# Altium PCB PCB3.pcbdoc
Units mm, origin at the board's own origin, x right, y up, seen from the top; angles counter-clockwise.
Board outline 92.7 x 92.7 mm, 2 copper layers (Top Layer, Bottom Layer); 80 components, 48 nets, 283 pads, 345 vias.
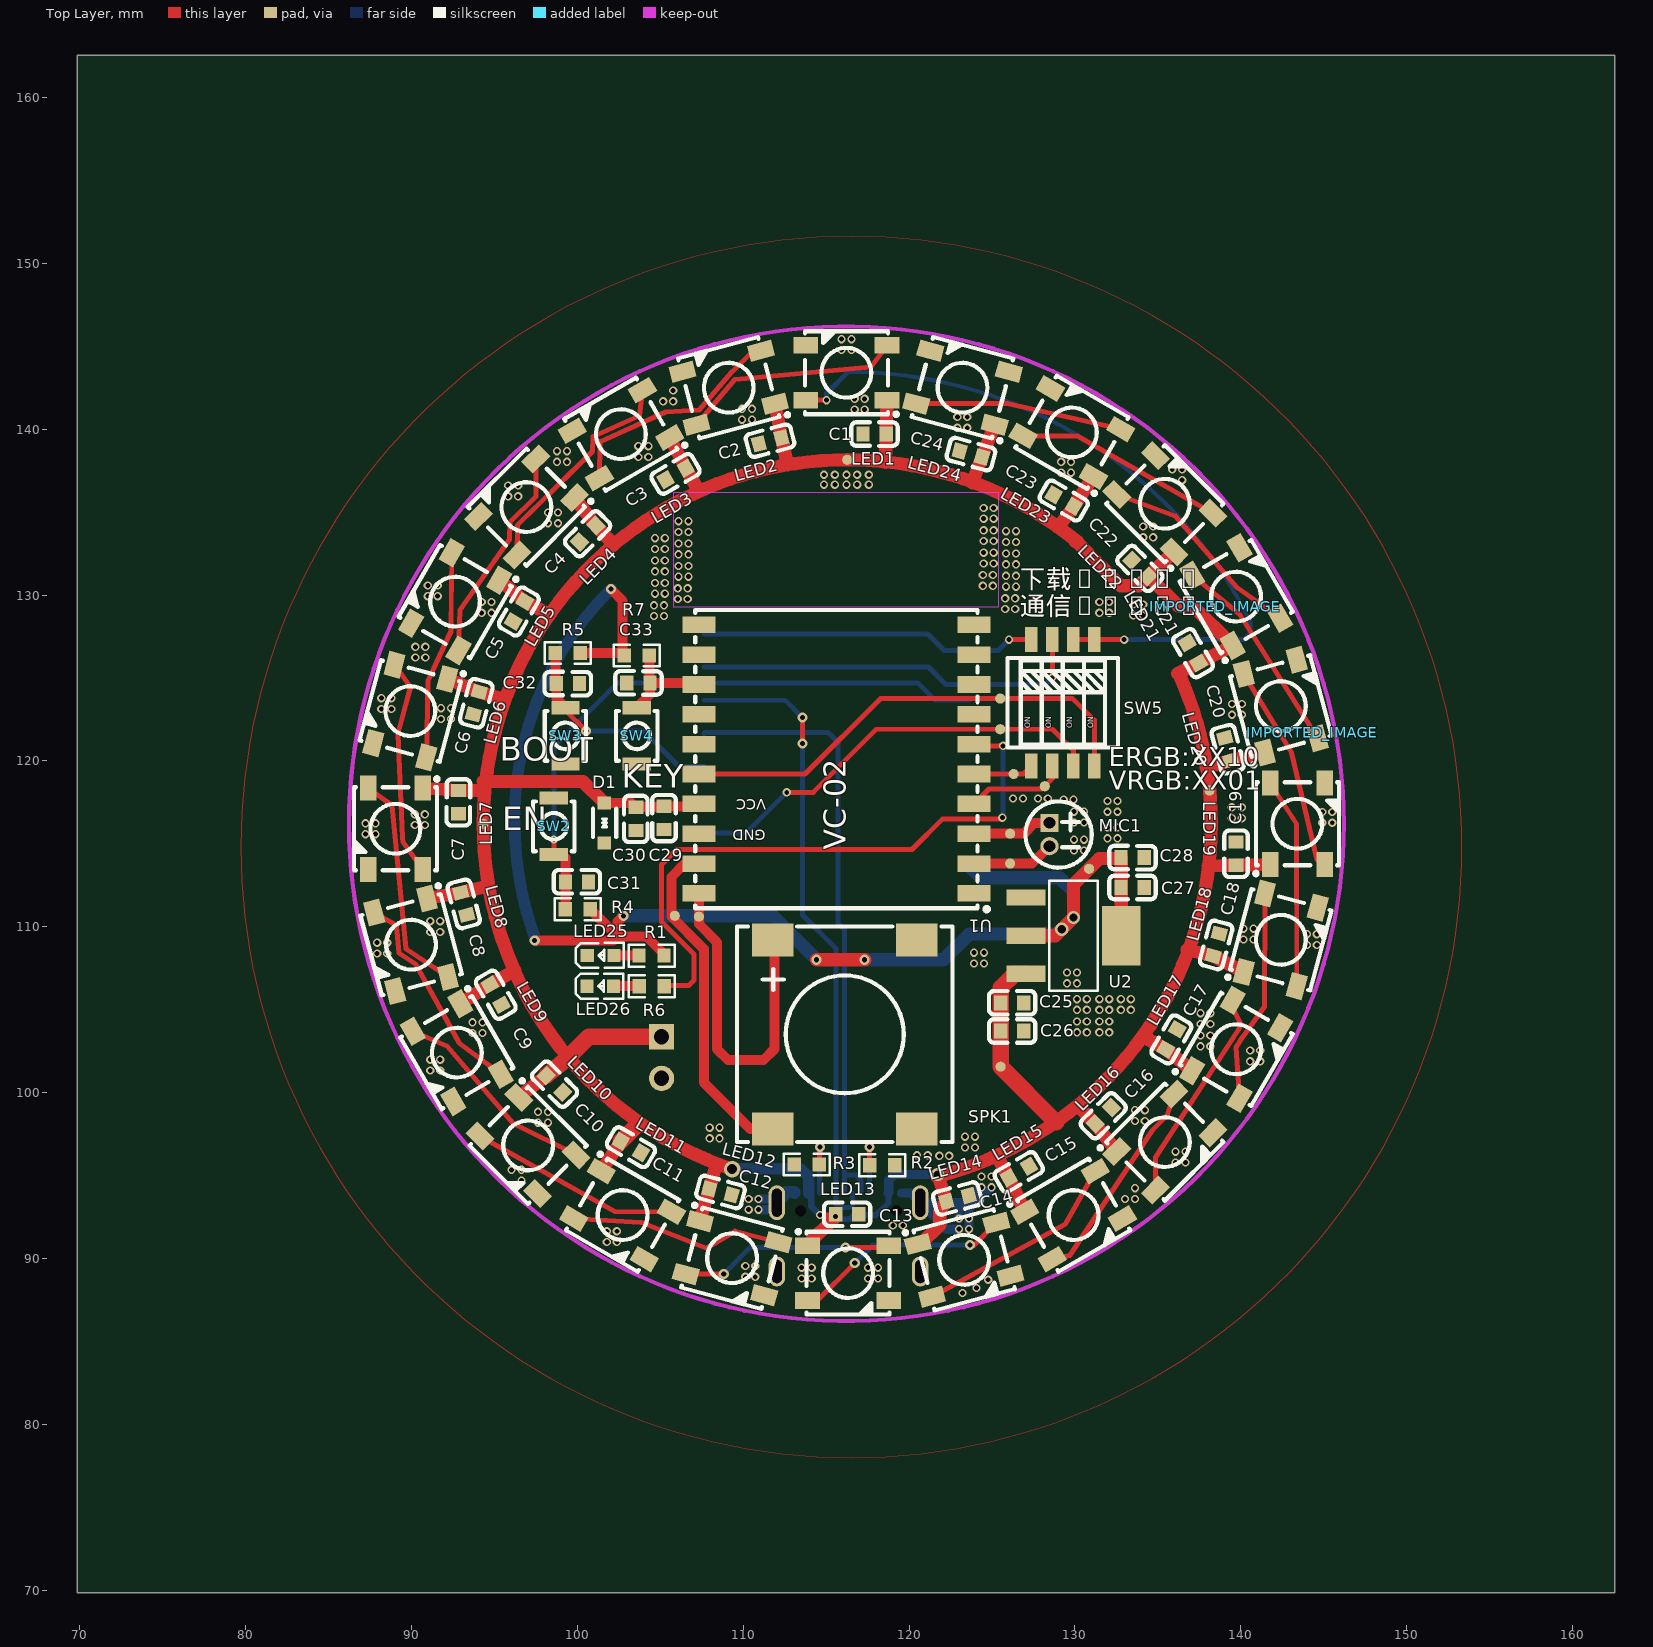
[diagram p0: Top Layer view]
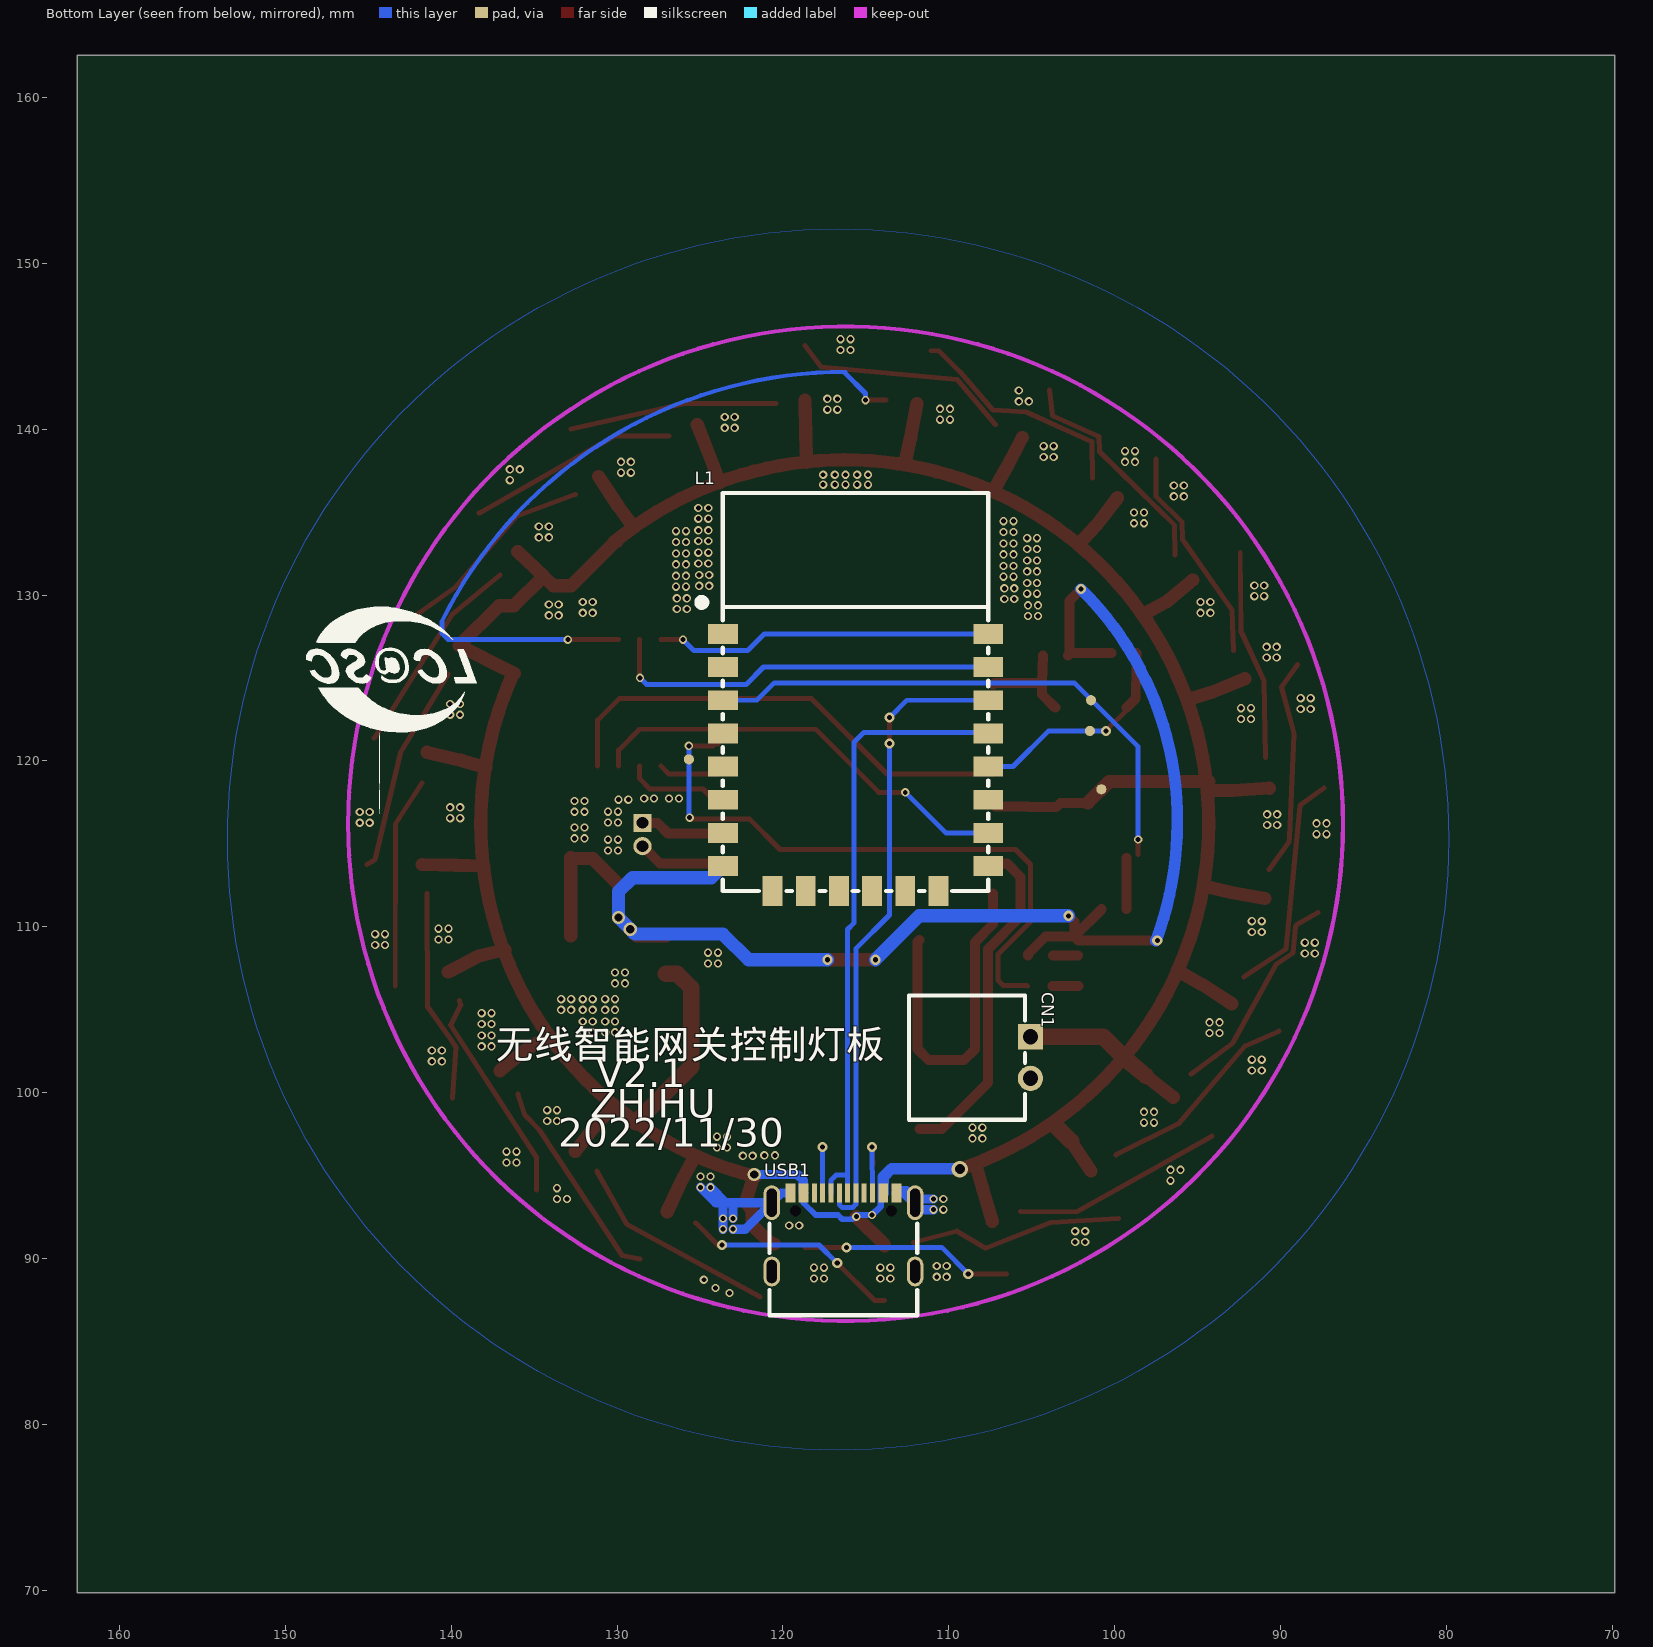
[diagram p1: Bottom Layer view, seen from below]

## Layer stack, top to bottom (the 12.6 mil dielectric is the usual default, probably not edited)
Top Layer: signal copper (thickness not stored)
Dielectric: dielectric 0.32, FR-4, Dk 4.8
Bottom Layer: signal copper (thickness not stored)

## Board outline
162.55,69.85 69.85,69.85 69.85,162.55 162.55,162.55

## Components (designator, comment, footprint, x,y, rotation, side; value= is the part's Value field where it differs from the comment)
C1 "CAP_0603" C0603 117.926,139.714 r0 top
C2 "CAP_0603" C0603 111.626,139.314 r15 top
C3 "CAP_0603" C0603 105.926,137.314 r30 top
C4 "CAP_0603" C0603 100.621,133.709 r45 top
C5 "CAP_0603" C0603 96.476,129.02 r60 top
C6 "CAP_0603" C0603 93.907,123.49 r75 top
C7 "CAP_0603" C0603 92.826,117.514 r90 top
C8 "CAP_0603" C0603 93.145,111.39 r105 top
C9 "CAP_0603" C0603 95.076,105.908 r120 top
C10 "CAP_0603" C0603 98.621,100.519 r135 top
C11 "CAP_0603" C0603 103.226,96.714 r150 top
C12 "CAP_0603" C0603 108.626,94.014 r165 top
C13 "CAP_0603" C0603 116.276,92.664 r0 top
C14 "CAP_0603" C0603 122.926,93.614 r15 top
C15 "CAP_0603" C0603 126.626,95.214 r30 top
C16 "CAP_0603" C0603 131.721,98.609 r45 top
C17 "CAP_0603" C0603 135.826,103.214 r60 top
C18 "CAP_0603" C0603 138.526,108.914 r75 top
C19 "CAP_0603" C0603 139.726,114.414 r90 top
C20 "CAP_0603" C0603 139.226,120.714 r105 top
C21 "CAP_0603" C0603 137.126,126.514 r120 top
C22 "CAP_0603" C0603 133.921,131.619 r135 top
C23 "CAP_0603" C0603 129.326,135.714 r150 top
C24 "CAP_0603" C0603 123.726,138.514 r165 top
C25 "CAP_0603" C0603 126.226,105.414 r0 top
C26 "CAP_0603" C0603 126.226,103.714 r0 top
C27 "CAP_0603" C0603 133.486,112.369 r0 top
C28 "CAP_0603" C0603 133.486,114.169 r0 top
C29 "CAP_0603" C0603 105.226,116.564 r90 top
C30 "CAP_0603" C0603 103.526,116.514 r90 top
C31 "CAP_0603" C0603 99.976,112.714 r0 top
C32 "CAP_0603" C0603 99.426,124.664 r0 top
C33 "CAP_0603" C0603 103.676,124.714 r180 top
CN1 "HDGC2501WR-2P" CONN-TH_2P-P2.50_HDGC2501WR-2P 105.076,102.114 r270 bottom
D1 "SESD3Z5C" SOD-323_L1.7-W1.3-LS2.5-BI 101.626,116.264 r270 top
IMPORTED_IMAGE "IMPORTED_IMAGE" IMPORTED_IMAGE 138.476,129.314 r0 top
IMPORTED_IMAGE "IMPORTED_IMAGE" IMPORTED_IMAGE 144.326,121.714 r0 top
L1 "ESP-C3-12F-2M" WIRELM-SMD_ESP-C3-12F-2M 115.626,119.914 r180 bottom
LED1 "WS2812B-B" LED-SMD_4P-L5.0-W5.0-TL_WS2812B-B 116.226,143.414 r180 top
LED2 "WS2812B-B" LED-SMD_4P-L5.0-W5.0-TL_WS2812B-B 109.126,142.514 r195 top
LED3 "WS2812B-B" LED-SMD_4P-L5.0-W5.0-TL_WS2812B-B 102.626,139.714 r210 top
LED4 "WS2812B-B" LED-SMD_4P-L5.0-W5.0-TL_WS2812B-B 96.926,135.314 r225 top
LED5 "WS2812B-B" LED-SMD_4P-L5.0-W5.0-TL_WS2812B-B 92.626,129.614 r240 top
LED6 "WS2812B-B" LED-SMD_4P-L5.0-W5.0-TL_WS2812B-B 89.926,123.014 r255 top
LED7 "WS2812B-B" LED-SMD_4P-L5.0-W5.0-TL_WS2812B-B 89.026,115.914 r270 top
LED8 "WS2812B-B" LED-SMD_4P-L5.0-W5.0-TL_WS2812B-B 89.966,108.92 r285 top
LED9 "WS2812B-B" LED-SMD_4P-L5.0-W5.0-TL_WS2812B-B 92.726,102.414 r300 top
LED10 "WS2812B-B" LED-SMD_4P-L5.0-W5.0-TL_WS2812B-B 97.026,96.814 r315 top
LED11 "WS2812B-B" LED-SMD_4P-L5.0-W5.0-TL_WS2812B-B 102.726,92.614 r330 top
LED12 "WS2812B-B" LED-SMD_4P-L5.0-W5.0-TL_WS2812B-B 109.326,90.014 r345 top
LED13 "WS2812B-B" LED-SMD_4P-L5.0-W5.0-TL_WS2812B-B 116.326,89.114 r0 top
LED14 "WS2812B-B" LED-SMD_4P-L5.0-W5.0-TL_WS2812B-B 123.326,89.914 r15 top
LED15 "WS2812B-B" LED-SMD_4P-L5.0-W5.0-TL_WS2812B-B 129.926,92.614 r30 top
LED16 "WS2812B-B" LED-SMD_4P-L5.0-W5.0-TL_WS2812B-B 135.426,97.014 r45 top
LED17 "WS2812B-B" LED-SMD_4P-L5.0-W5.0-TL_WS2812B-B 139.726,102.614 r60 top
LED18 "WS2812B-B" LED-SMD_4P-L5.0-W5.0-TL_WS2812B-B 142.426,109.214 r75 top
LED19 "WS2812B-B" LED-SMD_4P-L5.0-W5.0-TL_WS2812B-B 143.426,116.214 r90 top
LED20 "WS2812B-B" LED-SMD_4P-L5.0-W5.0-TL_WS2812B-B 142.426,123.314 r105 top
LED21 "WS2812B-B" LED-SMD_4P-L5.0-W5.0-TL_WS2812B-B 139.726,129.914 r120 top
LED22 "WS2812B-B" LED-SMD_4P-L5.0-W5.0-TL_WS2812B-B 135.426,135.514 r135 top
LED23 "WS2812B-B" LED-SMD_4P-L5.0-W5.0-TL_WS2812B-B 129.826,139.814 r150 top
LED24 "WS2812B-B" LED-SMD_4P-L5.0-W5.0-TL_WS2812B-B 123.226,142.514 r165 top
LED25 "LED_0603-R" LED0603-RD_BLUE 101.401,108.267 r0 top
LED26 "LED_0603-R" LED0603-RD_BLUE 101.376,106.414 r0 top
MIC1 "GMI4015P-2C-42db" MIC-TH_BD4.0-P1.40-D0.4-L-FD 128.476,115.564 r270 top
R1 "Res_0603" R0603 104.473,108.264 r0 top
R2 "Res_0603" R0603 118.376,95.614 r0 top
R3 "Res_0603" R0603 113.826,95.664 r180 top
R4 "Res_0603" R0603 100.026,111.064 r0 top
R5 "Res_0603" R0603 99.423,126.514 r0 top
R6 "Res_0603" R0603 104.492,106.419 r0 top
R7 "Res_0603" R0603 103.573,126.364 r180 top
SPK1 "FS-1340" BUZ-SMD_4P-L13.0-W13.0-P11.4-BL 116.126,103.514 r270 top
SW2 "B3U-1000P" KEY-SMD_B3U-1000PM 98.576,116.063 r90 top
SW3 "B3U-1000P" KEY-SMD_B3U-1000PM 99.276,121.514 r270 top
SW4 "B3U-1000P" KEY-SMD_B3U-1000PM 103.576,121.514 r270 top
SW5 "DSHP04TS-S" SW-SMD_8P-L6.7-W5.4-P1.27-LS8.5 129.276,123.514 r180 top
U1 "VC-02_CN" COMM-SMD_VC-02_CN 115.626,120.114 r180 top
U2 "AMS1117-2.5_C498436" SOT-223-3_L6.7-W3.7-P2.30-LS7.0-BR 129.926,109.464 r180 top
USB1 "TYPE-C16PIN" USB-C-SMD_TYPE-C16PIN 116.355,91.576 r180 bottom

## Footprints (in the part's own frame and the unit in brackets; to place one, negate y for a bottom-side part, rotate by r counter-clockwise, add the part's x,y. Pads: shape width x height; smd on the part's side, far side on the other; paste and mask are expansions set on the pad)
BUZ-SMD_4P-L13.0-W13.0-P11.4-BL [mm]
  rect 1.999x2.499 smd: 1(-5.7,-4.351) 2(5.7,-4.351) 3(5.7,4.351) 4(-5.7,4.351)
  silkscreen extent -6.5,-6.5 6.5,6.5
C0603 [mm]
  rect 0.8x0.9 smd: 1(-0.7,0) 2(0.7,0)
  silkscreen extent -1.41,-0.71 1.39,0.72
COMM-SMD_VC-02_CN [mm]
  rect 2x1 smd: 1(-8.3,8.1) 2(-8.3,6.3) 3(-8.3,4.5) 4(-8.3,2.7) 5(-8.3,0.9) 6(-8.3,-0.9) 7(-8.3,-2.7) 8(-8.3,-4.5) 9(-8.3,-6.3) 10(-8.3,-8.1) 11(8.3,-8.1) 12(8.3,-6.3) 13(8.3,-4.5) 14(8.3,-2.7) 15(8.3,-0.9) 16(8.3,0.9) 17(8.3,2.7) 18(8.3,4.5) 19(8.3,6.3) 20(8.3,8.1)
  silkscreen extent -9.19,-9 8.52,9.18
CONN-TH_2P-P2.50_HDGC2501WR-2P [mil]
  rect 60x60 hole 36: 1(-49.22,0)
  round 60 hole 36: 2(49.21,-0.01)
  silkscreen extent -148,-288 148,-13
IMPORTED_IMAGE [mm]
KEY-SMD_B3U-1000PM [mil]
  rect 31.5x66.9 smd: 1(-66.9,0) 2(66.9,0)
  silkscreen extent -59,-49 59,49
LED0603-RD_BLUE [mil]
  rect 31.5x31.5 smd: 1(-31.5,-0.1) 2(31.5,0.1)
  silkscreen extent -59,-29 55,30
LED-SMD_4P-L5.0-W5.0-TL_WS2812B-B [mm]
  rect 1.5x1 smd: 1(-2.45,1.65) 2(-2.45,-1.65) 3(2.45,-1.65) 4(2.45,1.65)
  silkscreen extent -3.1,-2.5 2.5,2.6
MIC-TH_BD4.0-P1.40-D0.4-L-FD [mm]
  rect 1.1x1.1 hole 0.7: 1(-0.7,0)
  round 1.1 hole 0.7: 2(0.7,0)
  silkscreen extent -2,-1.45 2,2.55
R0603 [mm]
  rect 0.806x0.864 smd: 1(-0.753,0) 2(0.753,0)
  silkscreen extent -1.39,-0.66 1.39,0.66
SOD-323_L1.7-W1.3-LS2.5-BI [mil]
  rect 31.5x31.5 smd: 1(-47.4,0) 2(47.4,0)
  silkscreen extent -34,-27 33,28
SOT-223-3_L6.7-W3.7-P2.30-LS7.0-BR [mm]
  rect 2.34x0.98 smd: 1(2.87,-2.3) 2(2.87,0) 3(2.87,2.3)
  rect 2.34x3.6 smd: 4(-2.87,0)
  silkscreen extent -1.47,-3.33 1.47,3.33
SW-SMD_8P-L6.7-W5.4-P1.27-LS8.5 [mm]
  rect 0.762x1.5 smd: 1(-1.905,-3.81) 2(-0.635,-3.81) 3(0.635,-3.81) 4(1.905,-3.81) 5(1.905,3.81) 6(0.635,3.81) 7(-0.635,3.81) 8(-1.905,3.81)
  silkscreen extent -3.33,-2.7 3.33,2.7
USB-C-SMD_TYPE-C16PIN [mil]
  oval 39.4x82.7 hole 23.6 slot 66.9 at 90 deg: 1(-170.1,70.4) 2(170.1,70.4)
  oval 39.4x70.9 hole 23.6 slot 55.1 at 90 deg: 3(-170.1,-93) 4(170.1,-93)
  rect 23.6x45.3 smd: A1B12(-126,93) A4B9(-94.5,93) B1A12(126,93) B4A9(94.5,93)
  rect 11.8x45.3 smd: A5(-49.2,93) A6(-9.8,93) A7(9.8,93) A8(-68.9,93) B5(68.9,93) B6(29.5,93) B7(-29.5,93) B8(49.2,93)
  Multi-Layer board cut-out: 101,50.7 102.27,56.25 105.82,60.71 110.95,63.18 116.65,63.18 121.78,60.71 125.33,56.25 126.6,50.7 126.6,50.7 125.33,45.15 121.78,40.69 116.65,38.22 110.95,38.22 105.82,40.69 102.27,45.15 101,50.7
  Multi-Layer board cut-out: -126.6,50.7 -125.33,56.25 -121.78,60.71 -116.65,63.18 -110.95,63.18 -105.82,60.71 -102.27,56.25 -101,50.7 -101,50.7 -102.27,45.15 -105.82,40.69 -110.95,38.22 -116.65,38.22 -121.78,40.69 -125.33,45.15 -126.6,50.7
  silkscreen extent -175,-197 175,20
WIRELM-SMD_ESP-C3-12F-2M [mil]
  rect 70.9x47.2 smd: 1(-315,305.1) 2(-315,226.4) 3(-315,147.6) 4(-315,68.9) 5(-315,-9.8) 6(-315,-88.6) 7(-315,-167.3) 8(-315,-246.1) 15(315,-246.1) 16(315,-167.3) 17(315,-88.6) 18(315,-9.8) 19(315,68.9) 20(315,147.6) 21(315,226.4) 22(315,305.1)
  rect 47.2x70.9 smd: 9(-196.8,-305.1) 10(-118.1,-305.1) 11(-39.4,-305.1) 12(39.4,-305.1) 13(118.1,-305.1) 14(196.9,-305.1)
  silkscreen extent -373,-305 315,640

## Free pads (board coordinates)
  round 0.61 smd far side: TP1(101.493,121.814) TP1(125.676,120.1) TP2(100.799,118.294) TP3(101.426,123.664)
  round 0.61 smd: TP3(130.862,113.5) TP4(125.526,101.564) TP5(138.126,118.214) TP6(116.276,138.164) TP9(94.326,116.214) TP10(125.5,121.914) TP11(125.5,123.764) TP12(126.311,119.214) TP13(128.188,118.476) TP15(126.1,115.614) TP16(126.1,113.814) TP19(105.876,110.664) TP20(107.326,110.613)

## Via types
v1: diameter 0.5, hole 0.3, Top Layer to Bottom Layer, 327 vias
v2: diameter 0.61, hole 0.305, Top Layer to Bottom Layer, 14 vias
v3: diameter 0.8, hole 0.5, Top Layer to Bottom Layer, 3 vias
v4: diameter 1, hole 0.6, Top Layer to Bottom Layer, 1 vias

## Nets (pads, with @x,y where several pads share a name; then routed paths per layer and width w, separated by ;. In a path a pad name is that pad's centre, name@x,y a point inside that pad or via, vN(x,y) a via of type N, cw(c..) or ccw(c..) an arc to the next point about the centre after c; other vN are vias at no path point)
3.3V: C27.1 C28.1 L1.8 pad.TP3@130.862,113.5 R1.2 R4.2 R5.2 R7.2 U2.2 U2.4 | length 93.4
  Top Layer w0.6: v2(97.426,109.164) 102.179,109.164 102.429,109.414 ; R5.2 102.669,126.514 R7.2@102.726,126.457 ; R4.2 102.429,109.414 ; v2(102.026,130.364) 102.726,129.664 R7.2@102.726,126.457 ; v2(102.776,110.664) 102.429,110.317 102.429,109.414 ; R7.2 R7.2@102.726,126.457 ; R1.2 105.226,108.364 104.176,109.414 102.429,109.414
  Top Layer w0.8: v2(114.426,108.014) v2(117.326,108.014) ; U2.2 128.826,109.464 v3(129.22,109.857) v3(129.926,110.564) 129.926,112.564 130.862,113.5 131.476,114.114 132.75,114.114 C28.1@132.796,114.159 ; C28.1 C28.1@132.796,114.159 ; U2.4 C28.1@132.796,114.159
  Bottom Layer w0.7: v2@97.512,109.159 cw(c116.226,116.214) 96.226,116.214 cw(c115.706,116.493) v2(102.026,130.364)
  Bottom Layer w0.8: v2(102.776,110.664) 111.776,110.664 v2(114.426,108.014) ; v2(117.326,108.014) 122.076,108.014 123.627,109.565 128.927,109.565 v3(129.22,109.857) v3(129.926,110.564) 129.926,112.114 129.076,112.964 124.326,112.964 L1.8
$1N2437: LED1.2 LED2.4 | length 13.4
  Top Layer w0.3: LED2.4 109.517,143.015 117.719,143.756 LED1.2
$1N2444: LED2.2 LED3.4 | length 13.9
  Top Layer w0.3: LED3.4 101.376,139.264 105.331,141.047 107.333,141.156 107.341,141.164 109.293,143.449 109.313,143.45 110.604,144.742 LED2.2
$1N2454: LED3.2 LED4.4 | length 13.7
  Top Layer w0.3: LED4.4 96.376,134.214 100.911,138.661 100.93,139.559 103.745,140.828 LED3.2
$1N2461: LED4.2 LED5.4 | length 13.1
  Top Layer w0.3: LED5.4 92.926,129.114 95.917,133.4 95.925,134.405 97.492,135.942 LED4.2
$1N2468: LED5.2 LED6.4 | length 12.7
  Top Layer w0.3: LED6.4 90.976,124.814 92.376,127.814 LED5.2
$1N2475: LED6.2 LED7.4 | length 13.1
  Top Layer w0.3: LED6.2 89.926,124.464 89.167,121.604 89.463,115.387 89.49,115.115 LED7.4
$1N2482: LED7.2 LED8.4 | length 13.5
  Top Layer w0.3: LED7.2 88.818,117.328 89.669,108.669 LED8.4
$1N2489: LED8.2 LED9.4 | length 13
  Top Layer w0.3: LED8.2 89.026,110.114 89.082,110.008 89.239,108.412 90.253,107.734 92.864,102.995 LED9.4
$1N3657: LED15.2 LED16.4 | length 12.7
  Top Layer w0.3: LED15.2 129.697,90.179 134.676,97.725 135.571,98.65 LED16.4
$1N3712: LED14.2 LED15.4 | length 12.8
  Top Layer w0.3: LED14.2 129.426,92.064 LED15.4
$1N3767: LED13.2 LED14.4 | length 13.3
  Top Layer w0.3: LED13.2 114.476,87.464 v2(116.726,89.714) ; v2(123.676,90.814) 123.938,90.814 LED14.4
  Bottom Layer w0.3: v2(116.726,89.714) 117.826,90.814 v2(123.676,90.814)
$1N3822: LED12.2 LED13.4 | length 13
  Top Layer w0.3: LED12.2 108.816,89.054 v2(108.826,89.064) ; v2(116.176,90.664) 118.676,90.664 LED13.4
  Bottom Layer w0.3: v2(108.826,89.064) 110.426,90.664 v2(116.176,90.664)
$1N3877: LED11.2 LED12.4 | length 13
  Top Layer w0.3: LED11.2 103.824,92.18 107.789,90.618 109.513,91.64 LED12.4
$1N3932: LED10.2 LED11.4 | length 12.7
  Top Layer w0.3: LED10.2 102.276,92.814 LED11.4
$1N3987: LED9.2 LED10.4 | length 12.6
  Top Layer w0.3: LED9.2 92.151,102.798 96.113,98.143 LED10.4
$1N6080: LED16.2 LED17.4 | length 13.1
  Top Layer w0.3: LED16.2 134.876,96.114 140.05,104.07 139.434,105.293 LED17.4
$1N7311: LED17.2 LED18.4 | length 12.9
  Top Layer w0.3: LED17.2 139.734,102.754 140.132,103.367 141.426,105.164 LED18.4
$1N7400: LED18.2 LED19.4 | length 12.7
  Top Layer w0.3: LED19.4 143.376,116.214 LED18.2
$1N7489: LED19.2 LED20.4 | length 12.7
  Top Layer w0.3: LED20.4 143.066,120.506 144.609,114.051 LED19.2
$1N7578: LED20.2 LED21.4 | length 12.6
  Top Layer w0.3: LED21.4 139.926,128.864 LED20.2
$1N7667: LED21.2 LED22.4 | length 12.7
  Top Layer w0.3: LED22.4 136.076,134.764 139.776,130.464 LED21.2
$1N7756: LED22.2 LED23.4 | length 12.7
  Top Layer w0.3: LED23.4 130.126,139.614 LED22.2
$1N8101: LED23.2 LED24.4 | length 12.5
  Top Layer w0.3: LED24.4 125.926,141.564 LED23.2
$1N43394: LED25.2 R1.1 | length 1.5
  Top Layer w0.6: LED25.2 103.714,108.269 R1.1
$1N51334: R2.1 USB1.A5 | length 3.9
  Top Layer w0.3: R2.1 v2(117.626,96.714)
  Bottom Layer w0.3: USB1.A5 v2(117.626,96.714)
$1N51787: R3.1 USB1.B5 | length 3.8
  Top Layer w0.3: R3.1 v2(114.626,96.714)
  Bottom Layer w0.3: USB1.B5 v2(114.626,96.714)
$1N57493: LED26.2 R6.1 | length 1.6
  Top Layer w0.6: LED26.2 103.736,106.416 R6.1
DIN: LED1.4 SW5.1 SW5.2 | length 45.1
  Top Layer w0.3: LED1.4 v1(115.026,141.764) ; SW5.2 SW5.1 132.966,127.324 v1(132.976,127.314)
  Bottom Layer w0.254: 116.226,143.464 cw(c116.315,116.384) 140.576,128.414
  Bottom Layer w0.3: v1(115.026,141.764) 115.026,142.164 116.276,143.414 ; v1(132.976,127.314) 140.191,127.314 140.576,127.699 140.576,128.414
EN: C31.1 L1.3 pad.TP3@101.426,123.664 R4.1 SW2.1 | length 36.7
  Top Layer w0.3: SW2.1 v1(98.576,115.263)
  Top Layer w0.6: R4.1 99.276,111.067 C31.1 SW2.1@99.276,114.165
  Bottom Layer w0.3: v1(98.576,115.263) 98.576,120.864 101.264,123.552 102.426,124.714 120.526,124.714 121.577,123.663 L1.3
ESP_RX: L1.21 SW5.3 | length 23.9
  Top Layer w0.3: v1(128.626,125.014) 128.641,125.029 SW5.3
  Bottom Layer w0.3: L1.21 121.175,125.664 122.226,124.614 128.226,124.614 v1(128.626,125.014)
ESP_TX: L1.22 SW5.4 | length 20.4
  Top Layer w0.3: v1(126.026,127.314) 127.361,127.314 SW5.4
  Bottom Layer w0.3: L1.22 121.126,127.663 122.126,126.664 125.376,126.664 v1(126.026,127.314)
GND: C1.1 C2.1 C3.1 C4.1 C5.1 C6.1 C7.1 C8.1 C9.1 C10.1 C11.1 C12.1 C13.2 C14.2 C15.2 C16.2 C17.2 C18.2 C19.2 C20.2 C21.2 C22.2 C23.2 C24.2 C25.2 C26.2 C27.2 C28.2 C29.1 C30.1 C31.2 C32.2 C33.2 CN1.2 D1.2 L1.15 LED1.3 LED2.3 LED3.3 LED4.3 LED5.3 LED6.3 LED7.3 LED8.3 LED9.3 LED10.3 LED11.3 LED12.3 LED13.3 LED14.3 LED15.3 LED16.3 LED17.3 LED18.3 LED19.3 LED20.3 LED21.3 LED22.3 LED23.3 LED24.3 LED25.1 LED26.1 R2.2 R3.2 SPK1.3 SPK1.4 SW2.2 SW3.2 SW4.2 U1.18 U2.1 USB1.1 USB1.2 USB1.A1B12 USB1.B1A12 | length 17
  Bottom Layer w0.559: v1(110.926,92.939) 111.61,92.939 USB1.2 111.81,93.589 v1(110.926,93.589) ; USB1.A1B12 120.102,93.938 USB1.1 ; v1(123.013,91.761) 122.279,91.761 USB1.1 ; v1(123.013,92.411) 123.013,93.277 122.926,93.364 ; v1(123.613,91.761) v1(123.613,92.411) 123.613,93.203 123.451,93.364 ; v1(124.376,94.289) 123.451,93.364 ; v1(124.976,94.289) 124.051,93.364 123.451,93.364 ; USB1.1 122.926,93.364 ; 122.926,93.364 123.451,93.364
  Bottom Layer w0.7: USB1.2 112.576,93.905 112.576,94.014 113.079,94.014 113.113,93.981 USB1.B1A12@113.113,93.938
  other v1: 123.226,87.914 124.076,88.214 124.776,88.714 113.526,88.789 114.126,88.789 117.527,88.789 118.127,88.789 110.126,88.889 110.726,88.889 113.526,89.439 114.126,89.439 117.527,89.439 118.127,89.439 110.126,89.539 110.726,89.539 101.776,90.989 102.376,90.989 101.776,91.639 102.376,91.639 119.026,91.989 119.626,91.989 110.326,92.939 110.326,93.589 133.026,93.589 133.626,93.589 133.626,94.239 96.626,94.689 124.376,94.939 124.976,94.939 96.026,95.339 96.626,95.339 136.076,95.789 136.676,95.789 121.826,96.189 122.426,96.189 120.476,96.214 121.126,96.214 136.076,96.439 136.676,96.439 123.376,96.689 123.976,96.689 107.976,97.239 108.576,97.239 123.376,97.339 123.976,97.339 107.976,97.889 108.576,97.889 97.626,98.189 98.226,98.189 133.626,98.289 134.226,98.289 97.626,98.839 98.226,98.839 133.626,98.939 134.226,98.939 91.126,101.339 91.726,101.339 140.576,101.889 141.176,101.889 91.126,101.989 91.726,101.989 140.576,102.539 141.176,102.539 137.576,102.789 138.176,102.789 137.576,103.439 138.176,103.439 93.676,103.589 94.276,103.589 130.126,103.639 130.726,103.639 131.476,103.639 132.076,103.639 137.576,104.139 138.176,104.139 93.676,104.239 94.276,104.239 130.126,104.289 130.726,104.289 131.476,104.289 132.076,104.289 137.576,104.789 138.176,104.789 130.126,104.989 130.726,104.989 131.476,104.989 132.076,104.989 132.776,104.989 133.376,104.989 130.126,105.639 130.726,105.639 131.476,105.639 132.076,105.639 132.776,105.639 133.376,105.639 129.526,106.589 130.126,106.589 129.526,107.239 130.126,107.239 123.926,107.789 124.526,107.789 87.926,108.389 88.526,108.389 123.926,108.439 124.526,108.439 143.997,108.902 144.597,108.902 87.926,109.039 88.526,109.039 140.176,109.239 140.776,109.239 143.997,109.552 144.597,109.552 91.126,109.689 91.726,109.689 140.176,109.889 140.776,109.889 91.126,110.339 91.726,110.339 129.954,114.604 130.554,114.604 129.954,115.254 130.554,115.254 131.976,115.339 132.576,115.339 87.226,115.588 87.826,115.588 131.976,115.989 132.576,115.989 90.196,116.134 90.796,116.134 87.226,116.238 87.826,116.238 144.926,116.275 145.526,116.275 129.954,116.296 130.554,116.296 139.473,116.555 140.073,116.555 90.196,116.784 90.796,116.784 144.926,116.925 145.526,116.925 129.954,116.946 130.554,116.946 131.976,116.939 132.576,116.939 139.473,117.205 140.073,117.205 131.976,117.589 132.576,117.589 129.326,117.664 129.926,117.664 126.276,117.739 126.876,117.739 127.776,117.739 128.376,117.739 91.776,122.539 92.376,122.539 139.476,122.789 140.076,122.789 88.176,123.139 88.776,123.139 91.776,123.189 92.376,123.189 139.476,123.439 140.076,123.439 88.176,123.789 88.776,123.789 90.226,126.239 90.826,126.239 90.226,126.889 90.826,126.889 104.626,128.739 105.226,128.739 133.526,128.789 134.126,128.789 94.226,128.939 94.826,128.939 131.476,128.939 132.076,128.939 125.803,129.164 126.403,129.164 104.626,129.389 105.226,129.389 133.526,129.439 134.126,129.439 94.226,129.589 94.826,129.589 131.476,129.589 132.076,129.589 106.053,129.764 106.653,129.764 125.803,129.814 126.403,129.814 90.976,129.939 91.576,129.939 104.676,130.089 105.276,130.089 106.053,130.414 106.653,130.414 125.853,130.514 126.453,130.514 124.453,130.564 125.053,130.564 90.976,130.589 91.576,130.589 104.676,130.739 105.276,130.739 106.103,131.114 106.703,131.114 125.853,131.164 126.453,131.164 124.453,131.214 125.053,131.214 104.676,131.439 105.276,131.439 106.103,131.764 106.703,131.764 125.853,131.864 126.453,131.864 124.503,131.914 125.103,131.914 104.676,132.089 105.276,132.089 106.103,132.464 106.703,132.464 125.853,132.514 126.453,132.514 124.503,132.564 125.103,132.564 104.676,132.789 105.276,132.789 106.103,133.114 106.703,133.114 125.853,133.214 126.453,133.214 124.503,133.264 125.103,133.264 104.676,133.439 105.276,133.439 134.126,133.489 134.726,133.489 106.103,133.814 106.703,133.814 125.853,133.864 126.453,133.864 124.503,133.914 125.103,133.914 134.126,134.139 134.726,134.139 98.226,134.339 98.826,134.339 106.103,134.464 106.703,134.464 124.503,134.614 125.103,134.614 98.226,134.989 98.826,134.989 124.503,135.264 125.103,135.264 95.826,135.964 96.426,135.964 95.826,136.614 96.426,136.614 114.876,136.664 115.526,136.664 116.226,136.664 116.876,136.664 117.576,136.664 136.476,136.939 114.876,137.264 115.526,137.264 116.226,137.264 116.876,137.264 117.576,137.264 129.176,137.389 129.776,137.389 135.876,137.589 136.476,137.589 98.776,138.039 99.376,138.039 129.176,138.039 129.776,138.039 103.676,138.339 104.276,138.339 98.776,138.689 99.376,138.689 103.676,138.989 104.276,138.989 122.913,140.093 123.513,140.093 109.926,140.589 110.526,140.589 122.913,140.743 123.513,140.743 116.726,141.189 117.326,141.189 109.926,141.239 110.526,141.239 105.176,141.689 105.776,141.689 116.726,141.839 117.326,141.839 105.776,142.339 115.925,144.789 116.525,144.789 115.925,145.439 116.525,145.439
GPIO_A25: pad.TP1@125.676,120.1 R6.2 U1.6 | length 37.6
  Top Layer w0.3: R6.2 105.29,106.464 106.726,106.464 107.024,106.762 107.024,108.364 105.076,110.312 105.074,110.364 105.074,113.762 105.976,114.664 120.176,114.664 122.026,116.514 v1@125.626,116.514 ; U1.6 124.126,121.014 124.226,120.914 v1(125.676,120.914)
  Bottom Layer w0.3: v1(125.626,116.578) 125.676,116.628 125.676,120.1 v1(125.676,120.914)
GPIO_A26: C33.1 R7.1 SW4.1 U1.13 | length 6.5
  Top Layer w0.6: SW4.1 104.376,124.013 C33.1 ; R7.1 C33.1 ; U1.13 107.226,124.714 C33.1
IO9: C32.1 L1.18 pad.TP1@101.493,121.814 R5.1 SW3.1 | length 13.5
  Top Layer w0.3: SW3.1 99.276,123.063 v2(100.526,121.814)
  Top Layer w0.6: R5.1 98.669,124.721 C32.1 98.726,123.763 SW3.1
  Bottom Layer w0.3: v2(100.526,121.814) 101.493,121.814 103.976,121.814 106.125,119.665 L1.18
MIC+: MIC1.1 pad.TP15 U1.3 | length 4.8
  Top Layer w0.6: U1.3 pad.TP15 126.925,115.614 127.575,116.264 MIC1.1
MIC-: MIC1.2 pad.TP16 U1.2 | length 5
  Top Layer w0.6: U1.2 pad.TP16 127.426,113.814 MIC1.2
RGB_E: L1.16 pad.TP10 SW5.7 | length 26.3
  Top Layer w0.3: v1(112.626,118.114) 114.226,118.114 118.026,121.914 pad.TP10 128.652,121.914 129.911,120.655 SW5.7
  Bottom Layer w0.3: L1.16 110.177,115.664 v1(112.626,118.114)
RGB_V: pad.TP11 SW5.8 U1.16 | length 29
  Top Layer w0.3: U1.16 113.726,119.214 118.276,123.764 pad.TP11 129.876,123.764 131.181,122.459 SW5.8
SPK+: pad.TP20 SPK1.1 U1.20 | length 20.5
  Top Layer w0.6: U1.20 pad.TP20 107.326,110.164 108.426,109.064 108.426,102.614 109.076,101.964 111.226,101.964 111.876,102.614 111.876,109.113 SPK1.1
SPK-: pad.TP19 SPK1.2 U1.19 | length 20.5
  Top Layer w0.6: U1.19 106.477,113.814 105.676,113.013 105.676,110.614 107.626,108.664 107.626,100.614 110.426,97.814 SPK1.2
USB_D+: L1.20 USB1.A6 USB1.B6 | length 38.4
  Top Layer w0.3: v2(113.576,121.064) v2(113.576,122.614)
  Bottom Layer w0.3: L1.20@107.626,123.664 112.526,123.664 v2(113.576,122.614) ; v2(113.576,121.064) 113.576,110.714 115.606,108.684 USB1.B6 115.606,93.259 115.804,93.061 116.423,93.061 116.604,93.242 USB1.A6
USB_D-: L1.19 USB1.A7 USB1.B7 | length 37.6
  Bottom Layer w0.3: L1.19 107.675,121.714 115.126,121.714 115.725,121.115 115.725,110.215 116.107,109.833 116.107,95.028 ; USB1.A7 116.107,95.028 ; USB1.B7 117.105,94.714 116.791,95.028 116.107,95.028
VC_RX: pad.TP12 SW5.5 U1.5 | length 3.6
  Top Layer w0.3: U1.5 pad.TP12 126.881,119.214 SW5.5
VC_TX: pad.TP13 SW5.6 U1.4 | length 6.1
  Top Layer w0.3: U1.4 124.826,118.314 128.026,118.314 128.641,118.929 SW5.6
VDD: C1.2 C2.2 C3.2 C4.2 C5.2 C6.2 C7.2 C8.2 C9.2 C10.2 C11.2 C12.2 C13.1 C14.1 C15.1 C16.1 C17.1 C18.1 C19.1 C20.1 C21.1 C22.1 C23.1 C24.1 C25.1 C26.1 C29.2 C30.2 CN1.1 D1.1 LED1.1 LED2.1 LED3.1 LED4.1 LED5.1 LED6.1 LED7.1 LED8.1 LED9.1 LED10.1 LED11.1 LED12.1 LED13.1 LED14.1 LED15.1 LED16.1 LED17.1 LED18.1 LED19.1 LED20.1 LED21.1 LED22.1 LED23.1 LED24.1 pad.TP4 pad.TP5 pad.TP6 pad.TP9 U1.17 U2.3 USB1.A4B9 USB1.B4A9 | length 263.9
  Top Layer w0.3: v1(114.626,92.614) 115.476,92.614 v1(115.576,92.514)
  Top Layer w0.6: D1.1 103.272,117.468 C30.2 105.176,117.214 C29.2 107.176,117.264 U1.17
  Top Layer w0.8: LED7.1 C7.2 94.376,118.214 ; LED8.1 C8.2 94.626,112.464 ; LED6.1 C6.2 95.576,123.714 ; LED9.1 C9.2 96.226,107.364 ; 94.326,118.764 100.33,118.764 D1.1 ; LED5.1 C5.2 98.226,128.864 ; LED10.1 C10.2 ; LED4.1 C4.2 102.176,133.064 ; LED11.1 C11.2 ; LED3.1 C3.2 107.185,136.503 ; LED12.1 C12.2 108.376,95.664 ; v4(109.335,95.39) cw(c116.276,116.214) pad.TP9 cw(c116.276,116.214) pad.TP6 cw(c116.276,116.214) 130.17,133.207 ; LED2.1 C2.2 112.676,137.864 ; LED13.1 113.876,90.814 v1(115.576,92.514) ; 118.576,138.014 C1.2 LED1.1 ; LED14.1 120.709,90.874 121.849,92.013 121.849,92.835 C14.1 v3(121.726,95.064) ; v3@121.67,94.937 ccw(c116.276,116.214) 138.226,116.214 ccw(c116.276,116.214) 136.293,125.222 ; 123.826,136.764 C24.1 LED24.1 ; 125.276,96.214 C15.1 LED15.1 ; 129.026,134.114 C23.1 LED23.1 ; 130.008,133.247 130.093,133.247 132.776,130.564 133.856,130.564 C22.1 ; 130.176,99.214 C16.1 LED16.1 ; 134.076,103.414 C17.1 LED17.1 ; LED22.1 C22.1 ; 136.202,125.277 C21.1 LED21.1 137.125,129.364 136.226,129.364 134.466,131.124 C22.1 ; 136.776,108.614 C18.1 LED18.1 ; 137.926,119.614 C20.1 LED20.1 ; 138.026,113.664 C19.1 LED19.1
  Top Layer w1: C10.2 99.376,102.064 100.676,103.364 CN1.1@105.076,103.364 ; C11.2 103.67,98.114 103.676,98.114 ; U2.3 126.376,107.164 125.535,106.323 125.535,105.423 C25.1 C26.1 pad.TP4 128.876,98.214
  Bottom Layer w0.35: v1(114.626,92.614) 115.576,92.614 115.826,92.364 116.427,92.364 116.676,92.614 118.026,92.614 118.756,93.344 USB1.A4B9
  Bottom Layer w0.4: USB1.B4A9 114.103,93.79 114.103,93.137 v1(114.626,92.614)
  Bottom Layer w0.559: USB1.A4B9 118.776,93.959 118.776,94.714 119.126,95.064 v3(121.726,95.064)
  Bottom Layer w0.68: v4@109.326,95.414 113.446,95.414 113.955,94.904 USB1.B4A9
"": L1.1 L1.2 L1.4 L1.5 L1.6 L1.7 L1.9 L1.10 L1.11 L1.12 L1.13 L1.14 L1.17 LED24.2 pad.TP2 U1.1 U1.7 U1.8 U1.9 U1.10 U1.11 U1.12 U1.14 U1.15 USB1.3 USB1.4 USB1.A8 USB1.B8

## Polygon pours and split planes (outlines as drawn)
GND on Bottom Layer (solid, remove dead copper, pour order 0): 153.5,115.264 ccw(c116.676,115.264) 79.852,115.264 ccw(c116.676,115.264)
GND on Top Layer (solid, remove dead copper, pour order 1): 153.35,114.814 ccw(c116.526,114.814) 79.702,114.814 ccw(c116.526,114.814)

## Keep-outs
Top Layer:
  region net "": 105.776,129.314 125.426,129.314 125.426,136.164 105.776,136.164
Board Outline Layer:
  circle w0.254 net "": c116.226,116.214 r30

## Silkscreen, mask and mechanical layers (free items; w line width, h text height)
Top Silkscreen Layer:
  text "下载:00xx" at 126.689,130.426 h1.15
  text "通信:11xx" at 126.681,128.791 h1.15
  text "BOOT" at 95.331,120.029 h1.44
  text "ERGB:XX10" at 132.045,119.676 h1.15
  text "KEY" at 102.678,118.379 h1.44
  text "VRGB:XX01" at 132.045,118.276 h1.15
  text "EN" at 95.474,115.829 h1.44
Bottom Silkscreen Layer:
  text "无线智能网关控制灯板" at 137.358,102.082 h1.73
  text "V2.1" at 131.236,100.332 h1.73
  text "ZHIHU" at 131.622,98.482 h1.73
  text "2022/11/30" at 133.548,96.732 h1.73
Mech6:
  lines w0.254 net "": 76.2,116.2 156.2,116.2 ; 87.879,87.879 116.2,116.2 ; 87.879,144.521 116.2,116.2 ; 116.2,76.2 116.2,156.2 ; 144.521,87.879 116.2,116.2 ; 144.521,144.521 116.2,116.2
